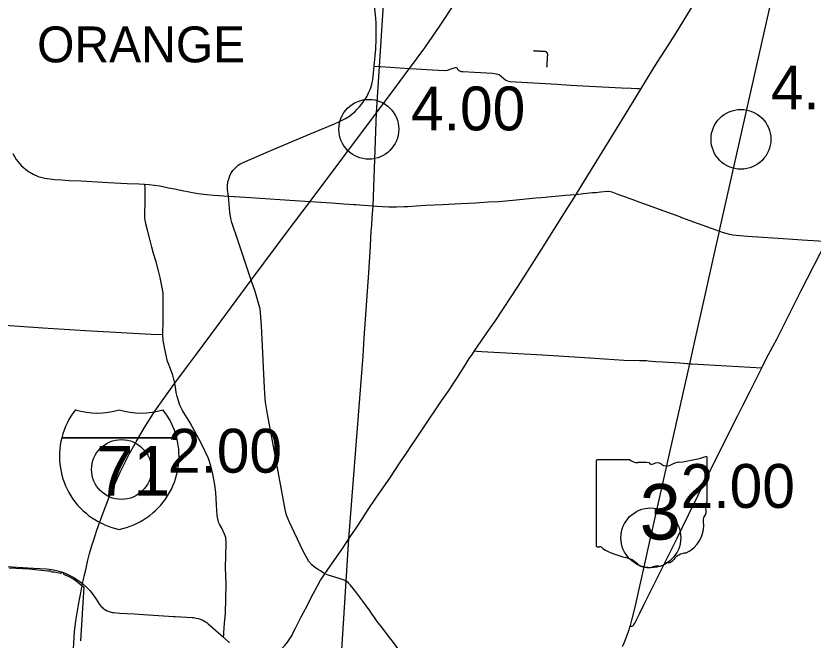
# Model space of a CAD drawing. Extents: x 1597222 to 1925846, y 496284 to 911751.
# Drawn here: x 1835573 to 1855559, y 784032 to 799690 of the extents above; entities that cross this region are included whole.
import ezdxf

# ---------------------------------------------------------------- set-up
doc = ezdxf.new("R2010")
doc.units = 0
for name, color, linetype in [('Default', 7, 'Continuous'), ('GM_X_Corporation', 7, 'Continuous'), ('GM_X_County_Road', 7, 'Continuous'), ('GM_X_Interstate_Route', 7, 'Continuous'), ('GM_X_Interstate_Shield', 7, 'Continuous'), ('GM_X_State_Route', 7, 'Continuous'), ('GM_X_State_Shield', 7, 'Continuous'), ('GM_X_Township', 7, 'Continuous'), ('GM_X_Township_Road', 7, 'Continuous'), ('GM_X_Township_Text', 7, 'Continuous')]:
    doc.layers.add(name, color=color, linetype=linetype)

msp = doc.modelspace()

# ---------------------------------------------------------------- linework, layer by layer
at = {"layer": 'Default'}
for centre in [(1844420, 796846), (1853750, 796595), (1838218, 788311), (1851491, 786598)]:
    msp.add_circle(centre, 750, dxfattribs=at)
at = {"layer": 'GM_X_Corporation'}
msp.add_lwpolyline([(1835406, 785847), (1835905, 785817), (1836363, 785772), (1836439, 785767), (1836438, 785752), (1836485, 785747), (1836530, 785742), (1836571, 785735), (1836613, 785728), (1836656, 785718), (1836693, 785710), (1836710, 785705), (1836712, 785746), (1836743, 785733), (1836768, 785721), (1836766, 785689), (1836880, 785635), (1837022, 785558), (1837123, 785488), (1837222, 785404), (1837273, 785365), (1837194, 784015)], dxfattribs=at)
at = {"layer": 'GM_X_County_Road'}
for points in [[(1851239, 797854), (1851501, 798281), (1851653, 798524), (1851853, 798834), (1852115, 799249), (1852419, 799742), (1852763, 800311), (1852954, 800610), (1853063, 800779)], [(1840901, 795167), (1840881, 795337), (1840878, 795422), (1840883, 795525), (1840907, 795596), (1840936, 795679), (1840963, 795735), (1841015, 795814), (1841074, 795882), (1841146, 795944), (1841188, 795971), (1841250, 796005), (1841459, 796098), (1841963, 796311), (1842716, 796630), (1842931, 796720), (1843559, 796986), (1843706, 797052), (1843837, 797118), (1843932, 797178), (1844005, 797233), (1844075, 797293), (1844123, 797340), (1844188, 797408), (1844248, 797481), (1844329, 797598), (1844353, 797638), (1844376, 797680), (1844415, 797758), (1844451, 797843), (1844467, 797886), (1844494, 797974), (1844505, 798018), (1844519, 798085), (1844557, 798429), (1844595, 798866), (1844607, 799102), (1844608, 799265), (1844601, 799518), (1844595, 799631), (1844566, 799941)], [(1843969, 786645), (1844100, 786841), (1844260, 787083), (1844407, 787305), (1844600, 787588), (1844962, 788122), (1845200, 788475), (1845400, 788775), (1845475, 788889), (1845613, 789100), (1845780, 789348), (1846245, 790032), (1846408, 790272), (1846638, 790612), (1846837, 790928), (1846939, 791093), (1847017, 791206), (1847071, 791285), (1847419, 791795), (1847605, 792061), (1848165, 792910), (1848753, 793830), (1849328, 794748), (1849622, 795214), (1849759, 795447), (1850577, 796772), (1850846, 797211), (1851239, 797854)], [(1851209, 784694), (1851326, 784936), (1852148, 786590), (1852443, 787187), (1853141, 788601), (1853675, 789667), (1853798, 789914), (1853979, 790280), (1854272, 790859), (1854392, 791103), (1854649, 791581), (1855260, 792799), (1855898, 794041), (1856273, 794777), (1856673, 795566), (1856869, 795971), (1857028, 796294)], [(1835496, 796238), (1835581, 796090), (1835702, 795941), (1835860, 795804), (1836005, 795717), (1836126, 795665), (1836296, 795616), (1836540, 795586), (1836718, 795575), (1836898, 795565), (1837211, 795550), (1837882, 795514), (1838358, 795490), (1838663, 795475), (1838800, 795467), (1838912, 795460), (1839037, 795444), (1839177, 795424), (1839395, 795378), (1839546, 795348), (1839738, 795311), (1840094, 795242), (1840210, 795224), (1840358, 795207), (1840537, 795193), (1840901, 795167)], [(1843318, 785694), (1843279, 785722), (1843205, 785766), (1843131, 785811), (1843049, 785869), (1842990, 785919), (1842913, 786003), (1842770, 786283), (1842422, 787009), (1842359, 787165), (1842321, 787304), (1842151, 788263), (1841879, 789699), (1841828, 790004), (1841819, 790093), (1841806, 790360), (1841726, 791923), (1841696, 792345), (1841656, 792486), (1841567, 792777), (1841473, 793063), (1841372, 793364), (1841315, 793534), (1841145, 794040), (1840989, 794505), (1840960, 794607), (1840938, 794769), (1840901, 795167)], [(1842589, 784346), (1842634, 784434), (1842728, 784617), (1842832, 784814), (1843028, 785192), (1843132, 785389), (1843208, 785531), (1843250, 785597), (1843318, 785694), (1843374, 785774), (1843742, 786301), (1843918, 786568), (1843969, 786645)], [(1830137, 786102), (1830408, 786127), (1830473, 786131), (1830595, 786143), (1830674, 786150), (1830727, 786150), (1830805, 786149), (1831205, 786125), (1831840, 786089), (1832575, 786043), (1833895, 785967), (1834638, 785924), (1835200, 785890), (1836012, 785840), (1836343, 785821), (1836473, 785802), (1836589, 785781), (1836648, 785764), (1836710, 785745), (1836767, 785724)], [(1836767, 785724), (1836786, 785717), (1836824, 785700)], [(1836824, 785700), (1836909, 785663), (1837004, 785613), (1837124, 785539), (1837243, 785449), (1837357, 785344), (1837425, 785273), (1837506, 785171), (1837585, 785055), (1837672, 784921), (1837711, 784875), (1837731, 784855), (1837753, 784836), (1837800, 784801), (1837815, 784791), (1837856, 784768), (1837907, 784747), (1837933, 784738), (1837960, 784731), (1837988, 784725), (1838015, 784721), (1838179, 784709), (1838542, 784687), (1838768, 784673), (1839525, 784627), (1839566, 784625), (1839988, 784599), (1840024, 784595), (1840057, 784590), (1840091, 784584), (1840142, 784571), (1840175, 784561), (1840207, 784550), (1840239, 784537), (1840288, 784514), (1840316, 784498), (1840369, 784463), (1840394, 784443), (1840518, 784334), (1840776, 784103), (1840930, 783961)], [(1843915, 785461), (1843910, 785466), (1843876, 785495), (1843850, 785510), (1843805, 785538), (1843756, 785553), (1843625, 785594), (1843533, 785620), (1843488, 785634), (1843403, 785662), (1843358, 785678), (1843318, 785694)], [(1845531, 783302), (1845441, 783422), (1845252, 783676), (1845103, 783878), (1845012, 784005), (1844911, 784131), (1844769, 784320), (1844631, 784501), (1844451, 784757), (1844268, 785009), (1844121, 785212), (1843999, 785361), (1843954, 785418), (1843915, 785461)], [(1850968, 784364), (1851009, 784379), (1851023, 784383), (1851040, 784392), (1851054, 784403), (1851062, 784412), (1851069, 784422), (1851092, 784460), (1851118, 784507), (1851150, 784573), (1851209, 784694)], [(1842518, 784205), (1842589, 784346)], [(1841308, 783054), (1841360, 783114), (1841434, 783206), (1841511, 783291), (1841584, 783354), (1841672, 783417), (1841829, 783524), (1842048, 783668), (1842113, 783713), (1842218, 783797), (1842316, 783897), (1842383, 783983), (1842415, 784029), (1842495, 784159), (1842518, 784205)]]:
    msp.add_lwpolyline(points, dxfattribs=at)
at = {"layer": 'GM_X_Interstate_Route'}
for points in [[(1845438, 798374), (1845825, 798892), (1846211, 799449), (1846552, 799972)], [(1837487, 786429), (1837514, 786520), (1837601, 786793), (1837756, 787221), (1837932, 787687), (1838187, 788245), (1838424, 788716), (1838589, 789007), (1838800, 789367), (1839053, 789775), (1839282, 790094), (1839487, 790389), (1839554, 790475), (1839800, 790800), (1840096, 791202), (1840599, 791880), (1841473, 793063), (1842402, 794310), (1842953, 795035), (1844609, 797255), (1845106, 797922), (1845407, 798332)], [(1845407, 798332), (1845438, 798374)], [(1837267, 785553), (1837294, 785668), (1837323, 785796), (1837371, 786001), (1837421, 786203), (1837487, 786429)], [(1837223, 785347), (1837233, 785398), (1837243, 785449), (1837267, 785553)], [(1837020, 783821), (1837027, 783953), (1837045, 784237), (1837075, 784514), (1837141, 784917), (1837223, 785347)]]:
    msp.add_lwpolyline(points, dxfattribs=at)
at = {"layer": 'GM_X_Interstate_Shield'}
for p, q in [((1836721, 789106), (1839606, 789106)), ((1839606, 789106), (1836721, 789106)), ((1839606, 789106), (1836721, 789106)), ((1836721, 789106), (1839606, 789106)), ((1839606, 789106), (1836721, 789106)), ((1839606, 789106), (1836721, 789106))]:
    msp.add_line(p, q, dxfattribs=at)
for centre, start, end in [((1838538, 788647), 141.669, 165.8066), ((1838538, 788647), 141.669, 165.8066), ((1837615, 791603), 253.0091, 286.9909), ((1837615, 791603), 253.0091, 286.9909), ((1838711, 791603), 253.0091, 286.9909), ((1838711, 791603), 253.0091, 286.9909), ((1837788, 788647), 14.1934, 38.331), ((1837788, 788647), 14.1934, 38.331), ((1838538, 788647), 165.8066, 258.463), ((1838538, 788647), 165.8066, 258.463), ((1837788, 788647), 281.537, 14.1934), ((1837788, 788647), 281.537, 14.1934)]:
    msp.add_arc(centre, 1875, start, end, dxfattribs=at)
at = {"layer": 'GM_X_State_Route'}
for points in [[(1853225, 794338), (1854573, 800349), (1855512, 804546), (1855541, 804679), (1855596, 804898), (1855689, 805139), (1855836, 805465), (1855908, 805599), (1856008, 805767), (1856148, 805978), (1856255, 806119), (1856504, 806413), (1857597, 807668), (1858467, 808668), (1858818, 809072), (1859440, 809788), (1860025, 810459)], [(1851027, 784561), (1851027, 784562), (1851101, 784861), (1851390, 786171), (1851399, 786214), (1851899, 788445), (1852470, 790966), (1852613, 791609), (1852746, 792202), (1852871, 792760), (1853072, 793659), (1853214, 794287), (1853225, 794338)], [(1850785, 783867), (1850801, 783904), (1850850, 784024), (1850893, 784139), (1850946, 784292), (1850968, 784364), (1850980, 784401), (1851027, 784561)]]:
    msp.add_lwpolyline(points, dxfattribs=at)
at = {"layer": 'GM_X_State_Shield'}
for p, q in [((1850120, 788518), (1850120, 786405)), ((1850120, 788518), (1850120, 786405)), ((1850963, 788554), (1850147, 788554)), ((1850963, 788554), (1850147, 788554)), ((1852904, 787501), (1852904, 788607)), ((1852904, 787501), (1852904, 788607)), ((1852904, 787501), (1852904, 787501)), ((1852904, 787501), (1852904, 787501))]:
    msp.add_line(p, q, dxfattribs=at)
for centre, radius, start, end in [((1850152, 788522), 32.3, 98.1301, 188.1301), ((1850152, 788522), 32.3, 98.1301, 188.1301), ((1851157, 788800), 313, 231.6195, 271.1119), ((1851157, 788800), 313, 231.6195, 271.1119), ((1851261, 787368), 1123, 80.4867, 94.9883), ((1851261, 787368), 1123, 80.4867, 94.9883), ((1851516, 788533), 90.3, 219.7921, 297.1024), ((1851516, 788533), 90.3, 219.7921, 297.1024), ((1851648, 788289), 188, 54.4667, 119.1411), ((1851648, 788289), 188, 54.4667, 119.1411), ((1852289, 787909), 594, 97.3462, 120.7689), ((1852289, 787909), 594, 97.3462, 120.7689), ((1851913, 791435), 2953, 275.8445, 288.9065), ((1851913, 791435), 2953, 275.8445, 288.9065), ((1852873, 788611), 31, 351.8621, 97.738), ((1852873, 788611), 31, 351.8621, 97.738), ((1851890, 788624), 226, 233.8562, 294.8282), ((1851890, 788624), 226, 233.8562, 294.8282), ((1852897, 787420), 48, 107.944, 210.337), ((1852897, 787420), 48, 107.944, 210.337), ((1852871, 787497), 33.2, 289.6038, 7.7341), ((1852871, 787497), 33.2, 289.6038, 7.7341), ((1852592, 787280), 288, 340.033, 23.6496), ((1852592, 787280), 288, 340.033, 23.6496), ((1853015, 787039), 210, 136.8065, 186.9296), ((1853015, 787039), 210, 136.8065, 186.9296), ((1852078, 786898), 739, 292.3089, 8.9858), ((1852078, 786898), 739, 292.3089, 8.9858), ((1850152, 786400), 32.5, 171.9584, 258.3066), ((1850152, 786400), 32.5, 171.9584, 258.3066), ((1850157, 786616), 248, 267.339, 280.6039), ((1850157, 786616), 248, 267.339, 280.6039), ((1850208, 786283), 89.5, 29.7484, 93.2717), ((1850208, 786283), 89.5, 29.7484, 93.2717), ((1851338, 788181), 2132, 240.4129, 257.1985), ((1851338, 788181), 2132, 240.4129, 257.1985), ((1850703, 785455), 667, 47.1842, 75.836), ((1850703, 785455), 667, 47.1842, 75.836), ((1851877, 786200), 239, 282.8732, 323.2771), ((1851877, 786200), 239, 282.8732, 323.2771), ((1852389, 785811), 404, 94.4031, 142.5768), ((1852389, 785811), 404, 94.4031, 142.5768), ((1851424, 786272), 423, 230.7004, 286.2918), ((1851424, 786272), 423, 230.7004, 286.2918), ((1851669, 785542), 348, 85.6951, 111.2099), ((1851669, 785542), 348, 85.6951, 111.2099), ((1851700, 786114), 226, 268.777, 315.5493), ((1851700, 786114), 226, 268.777, 315.5493), ((1851904, 785909), 63.5, 65.7517, 132.6484), ((1851904, 785909), 63.5, 65.7517, 132.6484)]:
    msp.add_arc(centre, radius, start, end, dxfattribs=at)
at = {"layer": 'GM_X_Township'}
msp.add_lwpolyline([(1843361, 777564), (1843430, 778709), (1843626, 781866), (1843694, 782979), (1843719, 783387), (1843850, 785510), (1843918, 786568), (1844278, 791160), (1844305, 791617), (1844418, 793241), (1844463, 793924), (1844479, 794298), (1844500, 794432), (1844507, 794629), (1844527, 794924), (1844609, 797255), (1844685, 798421), (1844785, 799970)], dxfattribs=at)
at = {"layer": 'GM_X_Township_Road'}
for points in [[(1848887, 798403), (1848888, 798408), (1848888, 798411), (1848888, 798413), (1848888, 798415), (1848888, 798418), (1848888, 798420), (1848889, 798423), (1848889, 798425), (1848889, 798427), (1848889, 798430), (1848889, 798432), (1848889, 798435), (1848889, 798437), (1848890, 798440), (1848890, 798442), (1848890, 798444), (1848890, 798447), (1848890, 798449), (1848890, 798452), (1848890, 798454), (1848891, 798457), (1848891, 798459), (1848891, 798461), (1848891, 798464), (1848891, 798466), (1848891, 798469), (1848891, 798471), (1848892, 798473), (1848892, 798476), (1848892, 798478), (1848892, 798481), (1848892, 798483), (1848892, 798486), (1848893, 798488), (1848893, 798491), (1848893, 798493), (1848893, 798496), (1848893, 798498), (1848893, 798501), (1848893, 798503), (1848894, 798506), (1848894, 798508), (1848894, 798511), (1848894, 798513), (1848894, 798516), (1848894, 798518), (1848894, 798521), (1848895, 798523), (1848895, 798526), (1848895, 798528), (1848895, 798531), (1848895, 798533), (1848895, 798535), (1848896, 798538), (1848896, 798540), (1848896, 798543), (1848896, 798545), (1848896, 798548), (1848896, 798550), (1848896, 798553), (1848897, 798555), (1848897, 798558), (1848897, 798560), (1848897, 798563), (1848897, 798565), (1848897, 798568), (1848897, 798570), (1848898, 798573), (1848898, 798575), (1848898, 798578), (1848898, 798580), (1848898, 798583), (1848898, 798585), (1848899, 798588), (1848899, 798590), (1848899, 798593), (1848899, 798595), (1848899, 798598), (1848899, 798600), (1848899, 798603), (1848900, 798605), (1848900, 798608), (1848900, 798610), (1848900, 798612), (1848900, 798615), (1848900, 798617), (1848900, 798620), (1848901, 798622), (1848901, 798625), (1848901, 798627), (1848901, 798630), (1848901, 798632), (1848901, 798635), (1848902, 798637), (1848902, 798640), (1848902, 798642), (1848902, 798645), (1848902, 798647), (1848902, 798650), (1848902, 798652), (1848903, 798655), (1848903, 798657), (1848903, 798660), (1848903, 798662), (1848903, 798665), (1848903, 798667), (1848903, 798670), (1848904, 798672), (1848904, 798675), (1848904, 798677), (1848904, 798680), (1848904, 798682), (1848904, 798685), (1848905, 798687), (1848905, 798690), (1848905, 798692), (1848905, 798694), (1848905, 798697), (1848905, 798699), (1848905, 798702), (1848906, 798704), (1848906, 798707), (1848906, 798709), (1848906, 798712), (1848906, 798714), (1848906, 798715), (1848906, 798716), (1848906, 798718), (1848906, 798719), (1848906, 798720), (1848906, 798722), (1848906, 798723), (1848906, 798724), (1848906, 798725), (1848906, 798727), (1848906, 798728), (1848906, 798729), (1848905, 798731), (1848905, 798732), (1848905, 798733), (1848905, 798734), (1848904, 798736), (1848904, 798737), (1848904, 798738), (1848903, 798740), (1848903, 798741), (1848903, 798742), (1848902, 798743), (1848902, 798745), (1848901, 798746), (1848901, 798747), (1848900, 798748), (1848900, 798749), (1848899, 798751), (1848899, 798752), (1848898, 798753), (1848898, 798754), (1848897, 798755), (1848896, 798756), (1848896, 798758), (1848895, 798759), (1848894, 798760), (1848893, 798761), (1848893, 798762), (1848892, 798763), (1848891, 798764), (1848890, 798765), (1848890, 798766), (1848889, 798767), (1848888, 798768), (1848887, 798769), (1848886, 798770), (1848885, 798771), (1848884, 798772), (1848883, 798773), (1848882, 798774), (1848881, 798775), (1848881, 798775), (1848880, 798776), (1848879, 798777), (1848877, 798778), (1848876, 798779), (1848875, 798780), (1848874, 798780), (1848873, 798781), (1848872, 798782), (1848871, 798782), (1848870, 798783), (1848869, 798784), (1848868, 798784), (1848867, 798785), (1848865, 798786), (1848864, 798786), (1848863, 798787), (1848862, 798787), (1848861, 798788), (1848859, 798788), (1848858, 798789), (1848857, 798789), (1848856, 798790), (1848854, 798790), (1848853, 798791), (1848852, 798791), (1848851, 798791), (1848849, 798792), (1848848, 798792), (1848847, 798792), (1848846, 798792), (1848844, 798793), (1848843, 798793), (1848842, 798793), (1848840, 798793), (1848839, 798793), (1848838, 798794), (1848837, 798794), (1848836, 798794), (1848833, 798794), (1848831, 798794), (1848828, 798794), (1848826, 798794), (1848823, 798794), (1848821, 798795), (1848818, 798795), (1848816, 798795), (1848813, 798795), (1848811, 798795), (1848808, 798795), (1848806, 798796), (1848803, 798796), (1848801, 798796), (1848798, 798796), (1848796, 798796), (1848793, 798796), (1848791, 798796), (1848788, 798797), (1848786, 798797), (1848783, 798797), (1848781, 798797), (1848778, 798797), (1848776, 798797), (1848773, 798797), (1848771, 798798), (1848768, 798798), (1848766, 798798), (1848763, 798798), (1848761, 798798), (1848758, 798798), (1848756, 798799), (1848753, 798799), (1848751, 798799), (1848748, 798799), (1848746, 798799), (1848744, 798799), (1848741, 798799), (1848739, 798800), (1848736, 798800), (1848734, 798800), (1848731, 798800), (1848729, 798800), (1848726, 798800), (1848724, 798801), (1848721, 798801), (1848719, 798801), (1848716, 798801), (1848714, 798801), (1848711, 798801), (1848709, 798801), (1848706, 798802), (1848704, 798802), (1848701, 798802), (1848699, 798802), (1848696, 798802), (1848694, 798802), (1848691, 798802), (1848689, 798803), (1848686, 798803), (1848684, 798803), (1848681, 798803), (1848679, 798803), (1848676, 798803), (1848674, 798804), (1848671, 798804), (1848669, 798804), (1848666, 798804), (1848664, 798804), (1848661, 798804), (1848659, 798804), (1848656, 798805), (1848654, 798805), (1848651, 798805), (1848649, 798805), (1848646, 798805), (1848644, 798805), (1848641, 798805), (1848639, 798806), (1848636, 798806), (1848634, 798806), (1848631, 798806), (1848629, 798806), (1848626, 798806), (1848624, 798807), (1848621, 798807), (1848619, 798807), (1848616, 798807), (1848614, 798807), (1848611, 798807), (1848609, 798807), (1848606, 798808), (1848604, 798808), (1848601, 798808), (1848599, 798808), (1848596, 798808), (1848594, 798808), (1848591, 798808), (1848589, 798809), (1848586, 798809), (1848584, 798809), (1848581, 798809), (1848579, 798809), (1848576, 798809), (1848574, 798810), (1848571, 798810), (1848569, 798810), (1848566, 798810), (1848564, 798810), (1848561, 798810), (1848559, 798810), (1848556, 798811), (1848551, 798811)], [(1844557, 798429), (1844685, 798421), (1844713, 798419)], [(1844713, 798419), (1845438, 798374), (1845605, 798366), (1846010, 798339), (1846326, 798317), (1846396, 798331), (1846458, 798351), (1846539, 798381), (1846621, 798407)], [(1846621, 798407), (1846648, 798353), (1846677, 798319), (1846739, 798297), (1846774, 798295)], [(1846774, 798295), (1847073, 798278), (1847525, 798251), (1847618, 798241), (1847692, 798217), (1847750, 798174), (1847804, 798120), (1847860, 798079), (1847901, 798061), (1847957, 798048), (1848107, 798036), (1849140, 797980), (1849475, 797956), (1849957, 797930), (1850759, 797887), (1851000, 797878), (1851156, 797870), (1851190, 797866), (1851239, 797854)], [(1839023, 793732), (1839022, 793733), (1838980, 793892), (1838938, 794052), (1838872, 794314), (1838831, 794473), (1838829, 794481), (1838820, 794525), (1838813, 794568), (1838807, 794613), (1838802, 794749), (1838809, 794981), (1838817, 795171), (1838814, 795349), (1838809, 795404), (1838800, 795467)], [(1849356, 795191), (1849466, 795202), (1849622, 795214), (1849804, 795234), (1849882, 795241), (1850029, 795258), (1850109, 795264), (1850232, 795277), (1850401, 795291), (1850433, 795290), (1850480, 795282), (1850513, 795274), (1850642, 795228), (1850705, 795204), (1850860, 795148), (1850918, 795128), (1851016, 795091), (1851187, 795029), (1852238, 794646), (1852263, 794637)], [(1840901, 795167), (1841330, 795144), (1842317, 795078)], [(1842317, 795078), (1842953, 795035), (1843483, 795000), (1843682, 794987), (1843794, 794978), (1844046, 794963), (1844099, 794959)], [(1844518, 794925), (1844527, 794924), (1844623, 794916), (1844766, 794911), (1844921, 794904), (1844972, 794902), (1845039, 794901), (1845111, 794902), (1845300, 794907), (1845407, 794912), (1845608, 794925), (1845850, 794939), (1846270, 794960), (1846729, 794982), (1847097, 795005), (1847420, 795024), (1847682, 795038), (1847858, 795053), (1848116, 795077), (1848609, 795123), (1848741, 795134), (1848838, 795144), (1848913, 795150), (1849273, 795182), (1849356, 795191)], [(1844099, 794959), (1844196, 794951), (1844299, 794944), (1844518, 794925)], [(1852263, 794637), (1853214, 794287)], [(1853214, 794287), (1853305, 794256), (1853460, 794213), (1853545, 794199), (1853631, 794186), (1853911, 794167)], [(1853911, 794167), (1854809, 794108), (1855052, 794090), (1855289, 794075), (1855696, 794051), (1855898, 794041), (1856800, 793974), (1856946, 793960)], [(1839261, 792049), (1839264, 792370), (1839264, 792732), (1839243, 792874), (1839189, 793128), (1839156, 793264), (1839087, 793520), (1839023, 793732)], [(1830989, 792193), (1830989, 792193), (1831659, 792153), (1833599, 792034), (1835168, 791938), (1836243, 791862), (1837317, 791801), (1838966, 791703), (1839258, 791696)], [(1839258, 791696), (1839261, 792049)], [(1839580, 790316), (1839554, 790475), (1839505, 790679), (1839409, 790947), (1839371, 791021), (1839307, 791326), (1839267, 791553), (1839258, 791696)], [(1847071, 791285), (1847137, 791277), (1847250, 791272), (1848774, 791185), (1849701, 791130), (1850088, 791107), (1850817, 791057), (1851208, 791046), (1851334, 791044), (1851380, 791042), (1851428, 791036), (1851605, 791018), (1851790, 791011), (1852221, 790984), (1852401, 790971), (1852418, 790969)], [(1852418, 790969), (1852428, 790967), (1852470, 790966), (1852519, 790965), (1854272, 790859)], [(1840776, 784103), (1840783, 784165), (1840786, 784226), (1840804, 784460), (1840825, 784699), (1840840, 785445), (1840831, 785855), (1840833, 786147), (1840842, 786466), (1840835, 786609), (1840806, 786690), (1840723, 786857), (1840679, 786939), (1840648, 786992), (1840620, 787160), (1840605, 787423), (1840587, 787735), (1840557, 787925), (1840498, 788237), (1840457, 788405), (1840405, 788583), (1840228, 788959), (1840110, 789170), (1839941, 789478), (1839747, 789795), (1839679, 789921), (1839616, 790145), (1839591, 790246), (1839580, 790316)]]:
    msp.add_lwpolyline(points, dxfattribs=at)

# ---------------------------------------------------------------- texts
at = {"layer": 'Default'}
for s, p in [('4.00', (1854500, 797345)), ('4.00', (1845480, 796819)), ('2.00', (1839382, 788232)), ('2.00', (1852241, 787348))]:
    msp.add_text(s, height=1100, dxfattribs=at).set_placement(p)
at = {"layer": 'GM_X_Interstate_Shield'}
msp.add_text('71', height=1250, dxfattribs=at).set_placement((1837586, 787653))
msp.add_text('71', height=1250, dxfattribs=at).set_placement((1837586, 787653))
at = {"layer": 'GM_X_State_Shield'}
msp.add_text('3', height=1392, dxfattribs=at).set_placement((1851212, 786554))
msp.add_text('3', height=1392, dxfattribs=at).set_placement((1851212, 786554))
at = {"layer": 'GM_X_Township_Text'}
msp.add_text('ORANGE', height=900, rotation=0, dxfattribs=at).set_placement((1836104, 798525))

doc.saveas('drawing.dxf')
